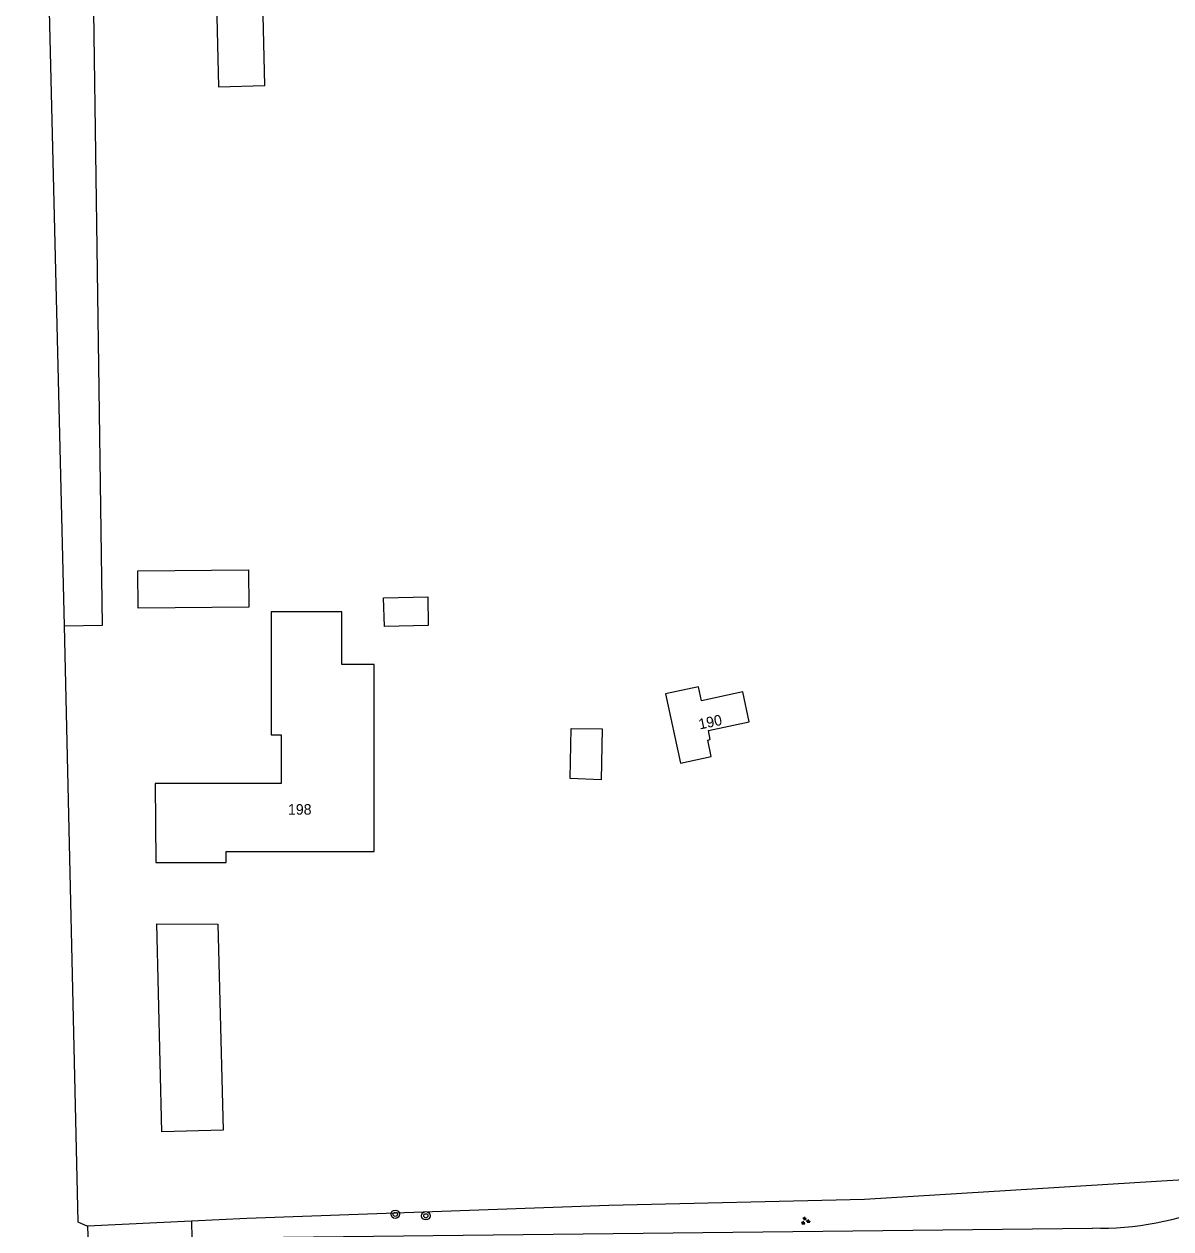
# Model space of a CAD drawing. Extents: x 128999 to 131010, y 395498 to 399007.
# Drawn here: x 130782.8 to 130891.5, y 395907.2 to 396021.5 of the extents above; entities that cross this region are included whole.
import ezdxf

# ---------------------------------------------------------------- set-up
doc = ezdxf.new("R2010")
doc.units = 0
for name, color, linetype in [('gg-afsc-hekwerk', 7, 'Continuous'), ('gg-anno-huisnummerreeks BGT', 7, 'Continuous'), ('gg-bbg-bijgebouw', 7, 'Continuous'), ('gg-bbg-gedigitaliseerde bebouwing', 7, 'Continuous'), ('gg-bbg-hoofdgebouw', 7, 'Continuous'), ('gg-bbg-luifel en loopbrug', 7, 'Continuous'), ('gg-knt-onverhard', 7, 'Continuous'), ('gg-knt-verharding', 7, 'Continuous'), ('gt-grn-groengrens', 7, 'Continuous'), ('gt-grn-vlakafsluiter', 7, 'Continuous'), ('gt-symb-boom', 7, 'Continuous'), ('gt-symb-groenvak', 7, 'Continuous')]:
    doc.layers.add(name, color=color, linetype=linetype)

# ---------------------------------------------------------------- blocks, each defined once
blk = doc.blocks.new('gt0-GRVAK')
at = {"layer": 'gt-symb-groenvak'}
for p, q in [((-0.11, 0.19), (-0.23, 0.24)), ((-0.18, 0.15), (0.09, 0.15)), ((-0.09, 0.21), (-0.16, 0.32)), ((-0.05, 0.21), (-0.05, 0.39)), ((0, 0.21), (0.06, 0.32)), ((0.01, 0.19), (0.13, 0.24)), ((0.26, -0.05), (0.2, 0.06)), ((0.31, -0.05), (0.31, 0.13)), ((0.35, -0.05), (0.41, 0.06)), ((-0.24, -0.23), (-0.36, -0.18)), ((-0.32, -0.26), (-0.05, -0.26)), ((-0.23, -0.21), (-0.29, -0.1)), ((-0.18, -0.2), (-0.18, -0.02)), ((-0.14, -0.21), (-0.07, -0.1)), ((-0.12, -0.23), (0, -0.18)), ((0.24, -0.07), (0.12, -0.02)), ((0.17, -0.11), (0.44, -0.11)), ((0.37, -0.07), (0.49, -0.02))]:
    blk.add_line(p, q, dxfattribs=at)
blk = doc.blocks.new('gt0-BOOM')
at = {"layer": 'gt-symb-boom'}
for radius in [0.4, 0.2]:
    blk.add_circle((0, 0), radius, dxfattribs=at)

msp = doc.modelspace()

# ---------------------------------------------------------------- linework, layer by layer
at = {"layer": 'gg-afsc-hekwerk'}
for p, q in [((130798.63, 395907.92), (130788.78, 395907.46)), ((130788.78, 395907.46), (130789.13, 395893.99))]:
    msp.add_line(p, q, dxfattribs=at)
msp.add_lwpolyline([(130896.58, 395942.79), (130894.75, 395911.98), (130862.43, 395909.98), (130838.21, 395909.42), (130803.87, 395908.16), (130798.63, 395907.92)], dxfattribs=at)
at = {"layer": 'gg-bbg-bijgebouw'}
for points in [[(130801.19, 396015.53), (130805.6, 396015.65), (130805.4, 396023.65), (130800.99, 396023.54), (130801.19, 396015.53)], [(130804.08, 395966.16), (130793.56, 395966.08), (130793.53, 395969.62), (130804.05, 395969.7), (130804.08, 395966.16)], [(130821.05, 395967.16), (130821.08, 395964.44), (130816.93, 395964.32), (130816.85, 395967.04), (130821.05, 395967.16)], [(130837.48, 395949.78), (130834.54, 395949.92), (130834.62, 395954.67), (130837.56, 395954.62), (130837.48, 395949.78)]]:
    msp.add_lwpolyline(points, dxfattribs=at)
at = {"layer": 'gg-bbg-gedigitaliseerde bebouwing'}
msp.add_lwpolyline([(130795.25, 395941.93), (130801.93, 395941.93), (130801.93, 395942.98), (130815.96, 395942.98), (130815.96, 395960.74), (130812.89, 395960.74), (130812.89, 395965.72), (130806.18, 395965.72), (130806.18, 395954.06), (130807.12, 395954.06), (130807.12, 395949.43), (130795.19, 395949.43), (130795.25, 395941.93)], dxfattribs=at)
at = {"layer": 'gg-bbg-hoofdgebouw'}
msp.add_lwpolyline([(130847.9, 395952.01), (130847.57, 395953.55), (130847.82, 395953.6), (130847.64, 395954.45), (130851.51, 395955.29), (130850.9, 395958.12), (130846.99, 395957.28), (130846.7, 395958.6), (130843.56, 395957.93), (130844.98, 395951.36), (130847.9, 395952.01)], dxfattribs=at)
at = {"layer": 'gg-bbg-luifel en loopbrug'}
msp.add_lwpolyline([(130795.33, 395936.12), (130801.13, 395936.08), (130801.63, 395916.54), (130795.83, 395916.39), (130795.33, 395936.12)], dxfattribs=at)
at = {"layer": 'gg-knt-onverhard'}
msp.add_line((130782.76, 396121.07), (130786.57, 395964.38), dxfattribs=at)
msp.add_lwpolyline([(130786.57, 395964.38), (130790.19, 395964.46), (130787.97, 396121.19)], dxfattribs=at)
at = {"layer": 'gg-knt-verharding'}
msp.add_line((130807.36, 395906.39), (130884.04, 395907.27), dxfattribs=at)
msp.add_arc((130884.89, 395934.65), 27.39, 268.2339, 293.6513, dxfattribs=at)
at = {"layer": 'gt-grn-groengrens'}
msp.add_line((130798.63, 395907.92), (130798.69, 395904.16), dxfattribs=at)
at = {"layer": 'gt-grn-vlakafsluiter'}
msp.add_lwpolyline([(130786.57, 395964.38), (130787.87, 395907.84), (130788.78, 395907.46)], dxfattribs=at)

# ---------------------------------------------------------------- block references
at = {"layer": 'gt-symb-boom'}
for p in [(130817.95, 395908.57), (130820.85, 395908.43)]:
    msp.add_blockref('gt0-BOOM', p, dxfattribs=at)
at = {"layer": 'gt-symb-groenvak'}
msp.add_blockref('gt0-GRVAK', (130856.82, 395907.94), dxfattribs=at)

# ---------------------------------------------------------------- texts
at = {"layer": 'gg-anno-huisnummerreeks BGT'}
msp.add_text('190', height=1, rotation=11.7, dxfattribs=at).set_placement((130846.82, 395954.56))
msp.add_text('198', height=1, dxfattribs=at).set_placement((130807.78, 395946.48))

doc.saveas('drawing.dxf')
